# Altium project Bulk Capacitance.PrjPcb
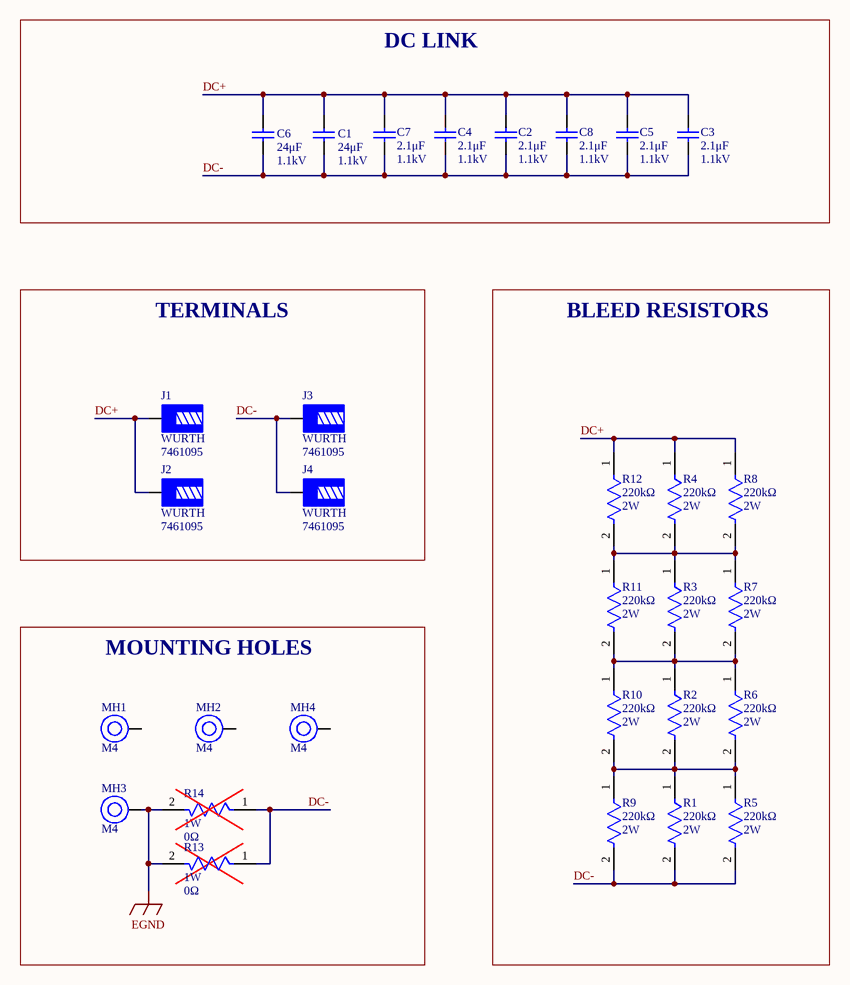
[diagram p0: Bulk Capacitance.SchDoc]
CAGE_CODE: ?????; CONTRACT_NUMBER: <CONTRACT NO>; DOC_NO_ASSY_DWG: <ASSY DWG NO>; DOC_NO_BOM: <BOM DOC NO>; DOC_NO_FAB_DWG: <FAB DWG NO>; DOC_NO_SCH_DWG: <SCH DWG NO>; PCB_2_DEC_TOL: +/-.01; PCB_3_DEC_TOL: +/-.010; PCB_ANG_TOL: +/-1/2; PCB_ASSEMBLY_NO: <PCB ASSY NO>; PCB_CHECKER: - -----; PCB_CHECKER_APP_DATE: --/--/----; PCB_DESIGNER: - -----; PCB_DESIGNER_APP_DATE: --/--/----; PCB_DWG_NO: <PCB DWG NO>; PCB_ENGINEER: - -----; PCB_ENGINEER_APP_DATE: --/--/----; PCB_PART_NUMBER: <PCB PN>; PCB_REV: A; SCH_REV: A
1 sheet, 30 parts. Net scope: global (net labels, ports and power ports of the same name join across sheets).
Board file: Bulk Capacitance.PcbDoc

## Sheet Bulk Capacitance.SchDoc: 60KW GMA DAB (BULK CAPACITANCE)
size 431 x 279 mm; Date: 10/2023; DocumentNumber: CRD60DD12N-GMA-BULK; Revision: 1; SheetNumber: 1; SheetTotal: 1; SheetSize: B

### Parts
C1  value 24μF  Voltage: 1.1kV  [C4AQQBW5240M3MJ]  (hidden comment: C4AQQBW5240M3MJ)
C2  value 2.1μF  Voltage: 1.1kV  [C4AQQLU4210M12J]  (hidden comment: C4AQQLU4210M12J)
C3  value 2.1μF  Voltage: 1.1kV  [C4AQQLU4210M12J]  (hidden comment: C4AQQLU4210M12J)
C4  value 2.1μF  Voltage: 1.1kV  [C4AQQLU4210M12J]  (hidden comment: C4AQQLU4210M12J)
C5  value 2.1μF  Voltage: 1.1kV  [C4AQQLU4210M12J]  (hidden comment: C4AQQLU4210M12J)
C6  value 24μF  Voltage: 1.1kV  [C4AQQBW5240M3MJ]  (hidden comment: C4AQQBW5240M3MJ)
C7  value 2.1μF  Voltage: 1.1kV  [C4AQQLU4210M12J]  (hidden comment: C4AQQLU4210M12J)
C8  value 2.1μF  Voltage: 1.1kV  [C4AQQLU4210M12J]  (hidden comment: C4AQQLU4210M12J)
J1  Manufacturer: WURTH  [7461095_chemical surface]  (hidden comment: 7461095)
J2  Manufacturer: WURTH  [7461095_chemical surface]  (hidden comment: 7461095)
J3  Manufacturer: WURTH  [7461095_chemical surface]  (hidden comment: 7461095)
J4  Manufacturer: WURTH  [7461095_chemical surface]  (hidden comment: 7461095)
MH1  Size: M4  [MH_M4_P]  (hidden comment: MH_M4_P)
MH2  Size: M4  [MH_M4_P]  (hidden comment: MH_M4_P)
MH3  Size: M4  [MH_M4_P]  (hidden comment: MH_M4_P)
MH4  Size: M4  [MH_M4_P]  (hidden comment: MH_M4_P)
R1  value 220kΩ  Power Rating: 2W  [FP-CRGP2512-IPC_C]  (hidden comment: CRGP2512F220K)
R2  value 220kΩ  Power Rating: 2W  [FP-CRGP2512-IPC_C]  (hidden comment: CRGP2512F220K)
R3  value 220kΩ  Power Rating: 2W  [FP-CRGP2512-IPC_C]  (hidden comment: CRGP2512F220K)
R4  value 220kΩ  Power Rating: 2W  [FP-CRGP2512-IPC_C]  (hidden comment: CRGP2512F220K)
R5  value 220kΩ  Power Rating: 2W  [FP-CRGP2512-IPC_C]  (hidden comment: CRGP2512F220K)
R6  value 220kΩ  Power Rating: 2W  [FP-CRGP2512-IPC_C]  (hidden comment: CRGP2512F220K)
R7  value 220kΩ  Power Rating: 2W  [FP-CRGP2512-IPC_C]  (hidden comment: CRGP2512F220K)
R8  value 220kΩ  Power Rating: 2W  [FP-CRGP2512-IPC_C]  (hidden comment: CRGP2512F220K)
R9  value 220kΩ  Power Rating: 2W  [FP-CRGP2512-IPC_C]  (hidden comment: CRGP2512F220K)
R10  value 220kΩ  Power Rating: 2W  [FP-CRGP2512-IPC_C]  (hidden comment: CRGP2512F220K)
R11  value 220kΩ  Power Rating: 2W  [FP-CRGP2512-IPC_C]  (hidden comment: CRGP2512F220K)
R12  value 220kΩ  Power Rating: 2W  [FP-CRGP2512-IPC_C]  (hidden comment: CRGP2512F220K)
R13  Max Power Dissipation: 1W  Resistance: 0Ω  [FP-RC2512-0_65-IPC_C]  (hidden comment: RC2512JK-070RL)
R14  Max Power Dissipation: 1W  Resistance: 0Ω  [FP-RC2512-0_65-IPC_C]  (hidden comment: RC2512JK-070RL)

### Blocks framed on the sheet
DC LINK: C1-C8
TERMINALS: J1-J4
BLEED RESISTORS: R1-R12
MOUNTING HOLES: MH1-MH4 R13 R14

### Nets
EGND: MH3.1 R13.2 R14.2
DC+: C1.1,2 C2.1 C3.1 C4.1 C5.1 C6.1,2 C7.1 C8.1 J1.1 J2.1 R4.1 R8.1 R12.1
DC-: C1.3,4 C2.2 C3.2 C4.2 C5.2 C6.3,4 C7.2 C8.2 J3.1 J4.1 R1.2 R5.2 R9.2 R13.1 R14.1
NetR1_1: R1.1 R2.2 R5.1 R6.2 R9.1 R10.2
NetR2_1: R2.1 R3.2 R6.1 R7.2 R10.1 R11.2
NetR3_1: R3.1 R4.2 R7.1 R8.2 R11.1 R12.2

Not connected (* = marked no-connect by the designer): MH1 1; MH2 1; MH4 1

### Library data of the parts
C1 C6 = C4AQQBW5240M3MJ: CAP FILM 24UF 5% 1.1KVDC RADIAL; Manufacturer: KEMET
C2-C5 C7 C8 = C4AQQLU4210M12J: CAP FILM 2.1UF 5% 1.1KVDC RADIAL; Manufacturer: KEMET
J1-J4 = CMP-03913-18187404-1: TERM REDCUBE M4 16PIN PCB; Insulation: Non-Insulated; Current Rating: 180A; Number of Contacts: 16
MH1-MH4 = MH_M4_P: M4 MOUNTING HOLE (HARDWARE TBD)
R1-R12 = CMP-03211-002966-1: RES 220K OHM 1% 2W 2512; Manufacturer: TE; Temperature Coefficient: ±100ppm/°C; Tolerance: 0.01; Voltage Rating: 500V
R13 R14 = CMP-2000-06974-2: RES SMD 0 OHM JUMPER 1W 2512; Manufacturer: YAGEO; Tolerance: 5%; Voltage Rating: 200V; Temperature Coefficient: 200ppm/°C; Value: 0Ω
